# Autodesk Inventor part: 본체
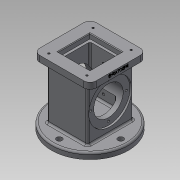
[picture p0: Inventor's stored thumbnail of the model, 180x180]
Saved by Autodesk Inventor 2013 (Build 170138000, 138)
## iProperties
Created: 2018-10
Part Number: 본체
Material: 일반
Document SubType Name: Modeling
Designer: Administrator
Density: 1 g/cm^3
Author: Administrator
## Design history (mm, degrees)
sketch "스케치1"
  geometry: C1 r 62.5 at (0, 0); 1 further point
  constraints: 1 centre point, 1 coincident
  dimensions: "d0" = 125 diameter of C1
extrude "돌출1" new body sketch "스케치1" distance "d1" = 10; taper "d2" = 0 deg
sketch "스케치2"
  geometry: L1 (-37, -33)-(37, -33); L2 (37, -33)-(37, 33); L3 (37, 33)-(-37, 33); L4 (-37, 33)-(-37, -33); L5 (-37, -33)-(37, 33); L6 (37, -33)-(-37, 33); C1 r 62.5 at (0, 0) reference
  constraints: 12 end point, 2 midpoint, 2 parallel, 1 horizontal, 1 perpendicular
  dimensions: "d3" = 74 distance of L3.end L2.end; "d4" = 66 distance of L2.end L1.end
extrude "돌출2" join sketch "스케치2" distance "d5" = 88; taper "d6" = 0 deg
sketch "스케치3"
  geometry: L1 (-46, -46)-(46, -46); L2 (46, -46)-(46, 46); L3 (46, 46)-(-46, 46); L4 (-46, 46)-(-46, -46); L5 (-46, -46)-(46, 46); L6 (46, -46)-(-46, 46); 1 further point
  constraints: 12 end point, 2 midpoint, 2 parallel, 1 horizontal, 1 perpendicular
  dimensions: "d7" = 92 distance of L3.end L2.end; "d8" = 92 distance of L2.end L1.end
extrude "돌출3" join sketch "스케치3" distance "d9" = 10; taper "d10" = 0 deg
sketch "스케치4"
  geometry: L1 (-26, -26)-(26, -26); L2 (26, -26)-(26, 26); L3 (26, 26)-(-26, 26); L4 (-26, 26)-(-26, -26); L5 (-26, -26)-(26, 26); L6 (26, -26)-(-26, 26); 1 further point
  constraints: 12 end point, 2 midpoint, 2 parallel, 1 horizontal, 1 perpendicular
  dimensions: "d11" = 52 distance of L2.end L3.end; "d13" = 52 distance between parallel lines of L1 L3
extrude "돌출4" cut sketch "스케치4" distance "d14" = 8; taper "d15" = 0 deg
sketch "스케치5"
  geometry: L1 (-22, -22)-(22, -22); L2 (22, -22)-(22, 22); L3 (22, 22)-(-22, 22); L4 (-22, 22)-(-22, -22); L5 (-22, -22)-(22, 22); L6 (22, -22)-(-22, 22); 1 further point
  constraints: 12 end point, 2 midpoint, 2 parallel, 1 horizontal, 1 perpendicular
  dimensions: "d16" = 44 distance of L3.end L2.end; "d17" = 44 distance of L2.end L1.end
extrude "돌출5" cut sketch "스케치5" distance "d18" = 74; taper "d19" = 0 deg
fillet "모깎기1" dims "d20" = 3
sketch "스케치6"
  geometry: L1 (13, -33)-(95, -33) reference; L2 (95, 33)-(13, 33) reference; L3 (54, -33)-(54, 33); L4 (89, 33)-(89, 30); L5 (89, 30)-(78, 30); L6 (78, 30)-(78, -30); L7 (78, -30)-(89, -30); L8 (89, -30)-(89, -33); 1 further point
  constraints: 12 end point, 3 parallel, 2 midpoint, 2 perpendicular, 2 point on line
  dimensions: "d21" = 3 distance between parallel lines of L2 L5; "d22" = 3 distance between parallel lines of L1 L7; "d23" = 70 diameter of L4 L3; "d24" = 70 diameter of L8 L3; "d25" = 48 diameter of L6 L3
revolve "회전1" sketch "스케치6" stored, may be unused: angle "d26" = 90 deg
sketch "스케치8"
  geometry: 2 further points
  dimensions: "d30" = 31 vertical distance of point (0, 0) point (36, 31); "d31" = 36 horizontal distance of point (0, 0) point (36, 31)
hole "구멍1" sketch "스케치8" at (36, 31) diameter "d32" = 3.242; stored, may be unused: countersink angle "d36" = 90 deg, drill point angle "d38" = 118 deg; dims "d33" = 4, "d34" = 4, "d35" = 2, "d37" = 6
sketch "스케치9"
  geometry: L1 (-62.5, 0)-(62.5, 0) reference; L2 (-28, 0)-(-24.826, 18); L3 (0, 0)-(0, 18); L4 (0, 18)-(-24.826, 18)
  constraints: 6 end point, 2 perpendicular, 1 midpoint, 1 point on line
  dimensions: "d43" = 80 deg angle of L1 L2; "d45" = 18 distance of L3.start L3.end; "d46" = 56 diameter of L2.start L3
revolve "회전2" sketch "스케치9" stored, may be unused: angle "d47" = 90 deg
sketch "스케치10"
  geometry: C1 r 35 at (0, 0) reference; 2 further points
  constraints: 1 horizontal alignment
  dimensions: "d48" = 29 distance of point (29, 0) C1.centre
hole "구멍2" sketch "스케치10" at (29, 0) diameter "d49" = 3.242; stored, may be unused: countersink angle "d53" = 90 deg, drill point angle "d55" = 118 deg; dims "d50" = 4, "d51" = 4, "d52" = 2, "d54" = 6
sketch "스케치13"
  geometry: L1 (-92.5, -13)-(32.5, -13) reference; 3 further points
  constraints: 1 midpoint, 1 vertical alignment
  dimensions: "d77" = 37 distance from line of L1 point (-30, 24)
hole "구멍5" sketch "스케치13" at (-30, 24) diameter "d78" = 4.134; stored, may be unused: countersink angle "d82" = 90 deg, drill point angle "d84" = 118 deg; dims "d79" = 18, "d80" = 4, "d81" = 2, "d83" = 6
sketch "스케치14"
  geometry: C1 r 2.067 at (-30, 24) reference; 2 further points
  constraints: 1 vertical alignment
  dimensions: "d85" = 43 distance of C1.centre point (-30, 67)
hole "구멍6" sketch "스케치14" at (-30, 67) diameter "d86" = 4.134; stored, may be unused: countersink angle "d90" = 90 deg, drill point angle "d92" = 118 deg; dims "d87" = 18, "d88" = 4, "d89" = 2, "d91" = 6
sketch "스케치15"
  geometry: C1 r 28 at (0, 0) reference; C2 r 4.5 at (0, 50)
  constraints: 1 centre point, 1 vertical alignment
  dimensions: "d93" = 9 diameter of C2; "d94" = 50 distance of C1.centre C2.centre
extrude "돌출7" cut sketch "스케치15" stored distance "d95" = 18; taper "d96" = 0 deg
sketch "스케치16"
  geometry: L1 (0, 10)-(92, 10) reference; L2 (0, 0)-(0, 10) reference; 2 further points
  constraints: 1 other
  dimensions: "d100" = 46 distance from line of L2 point (46, 6); "d101" = 4 distance from line of L1 point (46, 6)
feature "엠보싱1" sketch "스케치16" dims "d102" = 0.5, "d103" = 0
fillet "모깎기2" dims "d104" = 10
fillet "모깎기3" dims "d105" = 3
chamfer "모따기1" distance "d106" = 1; stored, may be unused: second distance "d107" = 2, angle "d108" = 45 deg
fillet "모깎기4" dims "d109" = 3
node "솔리드1"
mirror "대칭1"
mirror "대칭2"
pattern_circular "원형 패턴1" dims angle "d57" = 360 deg
mirror "대칭3"
pattern_circular "원형 패턴2" dims angle "d98" = 360 deg
node "작업 평면1"
node "작업 평면2"
node "작업 평면3"
